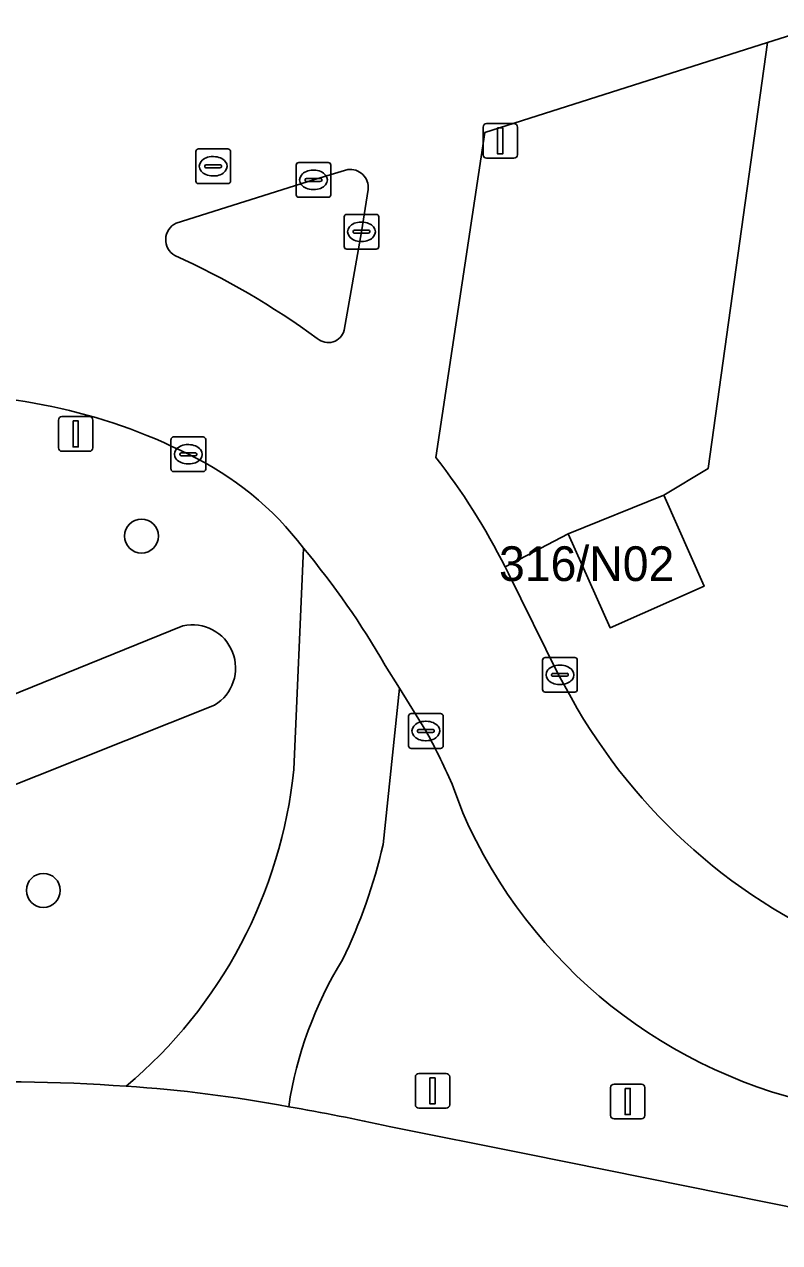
# Model space of a CAD drawing. Extents: x 161090 to 161692, y 379509 to 380907.
# Drawn here: x 161482.51 to 161504.29, y 379810.76 to 379845.87 of the extents above; entities that cross this region are included whole.
import ezdxf

# ---------------------------------------------------------------- set-up
doc = ezdxf.new("R2010")
doc.units = 0
for name, color, linetype in [('IMGEO_Boom', 7, 'Continuous'), ('IMGEO_Groenvoorziening', 7, 'Continuous'), ('IMGEO_Kolk', 7, 'Continuous'), ('IMGEO_Lichtmast', 7, 'Continuous'), ('IMGEO_Pand', 7, 'Continuous'), ('IMGEO_Pand_nummerreeks', 7, 'Continuous'), ('IMGEO_Rijbaan_lokaal_gesloten', 7, 'Continuous'), ('IMGEO_Rioolput', 7, 'Continuous'), ('IMGEO_Verkeerseiland_groen', 7, 'Continuous'), ('IMGEO_Verkeerseiland_open', 7, 'Continuous'), ('IMGEO_Voetpad_halfverhard', 7, 'Continuous'), ('IMGEO_Waterloop', 7, 'Continuous')]:
    doc.layers.add(name, color=color, linetype=linetype)

msp = doc.modelspace()

# ---------------------------------------------------------------- linework, layer by layer
at = {"layer": 'IMGEO_Boom'}
for centre in [(161485.888, 379831.123), (161483.057, 379820.91)]:
    msp.add_circle(centre, 0.489, dxfattribs=at)
at = {"layer": 'IMGEO_Groenvoorziening'}
for points in [[(161514.99, 379848.832), (161503.939, 379845.347), (161502.232, 379833.068), (161500.956, 379832.3), (161502.113, 379829.674), (161499.404, 379828.481), (161498.199, 379831.187), (161496.375, 379830.233), (161496.47, 379830.041), (161497.906, 379827.145), (161498.28, 379826.466)], [(161503.939, 379845.347), (161495.787, 379842.75), (161494.38, 379833.386)], [(161496.375, 379830.233), (161498.199, 379831.187), (161500.956, 379832.3), (161502.232, 379833.068), (161503.939, 379845.347)], [(161490.284, 379824.397), (161490.559, 379830.777)], [(161487.997, 379826.248), (161463.782, 379816.609), (161462.95, 379818.759), (161487.084, 379828.537)]]:
    msp.add_lwpolyline(points, dxfattribs=at)
for centre, radius, start, end in [((161480.014, 379819.128), 16.069, 63.2743, 93.106), ((161483.32, 379825.278), 9.091, 37.2239, 64.4573), ((161479.54, 379821.788), 18.834, 26.6382, 38.0073), ((161487.354, 379827.318), 1.248, 301.0173, 102.4732), ((161512.831, 379834.579), 16.66, 209.1437, 248.1335), ((161476.574, 379825.81), 13.782, 310.0851, 354.1164), ((161481.636, 379760.171), 55.226, 86.0407, 92.3337)]:
    msp.add_arc(centre, radius, start, end, dxfattribs=at)
at = {"layer": 'IMGEO_Kolk'}
for p, q in [((161490.349, 379840.962), (161490.349, 379841.814)), ((161490.424, 379841.888), (161491.276, 379841.888)), ((161490.837, 379841.668), (161490.862, 379841.668)), ((161491.35, 379841.814), (161491.35, 379840.962)), ((161490.608, 379841.382), (161490.608, 379841.394)), ((161491.046, 379841.345), (161490.648, 379841.345)), ((161490.651, 379841.431), (161491.049, 379841.431)), ((161491.092, 379841.394), (161491.092, 379841.382)), ((161490.86, 379841.108), (161490.835, 379841.108)), ((161491.276, 379840.888), (161490.424, 379840.888)), ((161491.732, 379839.468), (161491.732, 379840.32)), ((161491.807, 379840.394), (161492.659, 379840.394)), ((161492.733, 379840.32), (161492.733, 379839.468)), ((161491.991, 379839.888), (161491.991, 379839.9)), ((161492.034, 379839.937), (161492.432, 379839.937)), ((161492.22, 379840.174), (161492.245, 379840.174)), ((161492.475, 379839.9), (161492.475, 379839.888)), ((161492.429, 379839.851), (161492.031, 379839.851)), ((161492.243, 379839.614), (161492.218, 379839.614)), ((161492.659, 379839.394), (161491.807, 379839.394)), ((161486.739, 379833.054), (161486.739, 379833.906)), ((161486.814, 379833.98), (161487.666, 379833.98)), ((161487.74, 379833.906), (161487.74, 379833.054)), ((161487.227, 379833.76), (161487.252, 379833.76)), ((161486.998, 379833.474), (161486.998, 379833.486)), ((161487.436, 379833.437), (161487.038, 379833.437)), ((161487.041, 379833.523), (161487.439, 379833.523)), ((161487.25, 379833.2), (161487.225, 379833.2)), ((161487.482, 379833.486), (161487.482, 379833.474)), ((161487.666, 379832.98), (161486.814, 379832.98)), ((161497.531, 379827.623), (161498.383, 379827.623)), ((161497.456, 379826.697), (161497.456, 379827.549)), ((161497.944, 379827.403), (161497.969, 379827.403)), ((161498.457, 379827.549), (161498.457, 379826.697)), ((161497.715, 379827.117), (161497.715, 379827.129)), ((161498.153, 379827.08), (161497.755, 379827.08)), ((161497.758, 379827.166), (161498.156, 379827.166)), ((161498.199, 379827.129), (161498.199, 379827.117)), ((161498.383, 379826.623), (161497.531, 379826.623)), ((161497.967, 379826.843), (161497.942, 379826.843)), ((161493.59, 379825.078), (161493.59, 379825.93)), ((161493.665, 379826.004), (161494.517, 379826.004)), ((161494.591, 379825.93), (161494.591, 379825.078)), ((161493.849, 379825.498), (161493.849, 379825.51)), ((161493.892, 379825.547), (161494.29, 379825.547)), ((161494.078, 379825.784), (161494.103, 379825.784)), ((161494.333, 379825.51), (161494.333, 379825.498)), ((161494.287, 379825.461), (161493.889, 379825.461)), ((161494.101, 379825.224), (161494.076, 379825.224)), ((161494.517, 379825.004), (161493.665, 379825.004))]:
    msp.add_line(p, q, dxfattribs=at)
for points in [[(161490.349, 379840.962), (161490.349, 379841.814)], [(161490.424, 379841.888), (161491.276, 379841.888)], [(161491.35, 379841.814), (161491.35, 379840.962)], [(161491.276, 379840.888), (161490.424, 379840.888)], [(161491.732, 379839.468), (161491.732, 379840.32)], [(161491.807, 379840.394), (161492.659, 379840.394)], [(161492.733, 379840.32), (161492.733, 379839.468)], [(161492.659, 379839.394), (161491.807, 379839.394)], [(161486.739, 379833.054), (161486.739, 379833.906)], [(161486.814, 379833.98), (161487.666, 379833.98)], [(161487.74, 379833.906), (161487.74, 379833.054)], [(161487.666, 379832.98), (161486.814, 379832.98)], [(161497.531, 379827.623), (161498.383, 379827.623)], [(161497.456, 379826.697), (161497.456, 379827.549)], [(161498.457, 379827.549), (161498.457, 379826.697)], [(161498.383, 379826.623), (161497.531, 379826.623)], [(161493.59, 379825.078), (161493.59, 379825.93)], [(161493.665, 379826.004), (161494.517, 379826.004)], [(161494.591, 379825.93), (161494.591, 379825.078)], [(161494.517, 379825.004), (161493.665, 379825.004)]]:
    msp.add_lwpolyline(points, dxfattribs=at)
for centre, radius, start, end in [((161490.426, 379841.812), 0.0765, 91.552, 178.448), ((161490.426, 379841.812), 0.0765, 91.552, 178.448), ((161491.274, 379841.812), 0.0765, 1.552, 88.448), ((161491.274, 379841.812), 0.0765, 1.552, 88.448), ((161490.648, 379841.391), 0.0403, 85.8775, 175.7526), ((161490.645, 379841.381), 0.0366, 178.938, 274.7102), ((161491.049, 379841.388), 0.043, 264.8664, 352.4533), ((161491.053, 379841.393), 0.0386, 1.7309, 96.639), ((161490.426, 379840.964), 0.0765, 181.552, 268.448), ((161490.426, 379840.964), 0.0765, 181.552, 268.448), ((161491.274, 379840.964), 0.0765, 271.552, 358.448), ((161491.274, 379840.964), 0.0765, 271.552, 358.448), ((161491.809, 379840.318), 0.0765, 91.552, 178.448), ((161491.809, 379840.318), 0.0765, 91.552, 178.448), ((161492.657, 379840.318), 0.0765, 1.552, 88.448), ((161492.657, 379840.318), 0.0765, 1.552, 88.448), ((161492.031, 379839.897), 0.0403, 85.8775, 175.7526), ((161492.028, 379839.887), 0.0366, 178.938, 274.7102), ((161492.432, 379839.894), 0.043, 264.8664, 352.4533), ((161492.436, 379839.899), 0.0386, 1.7309, 96.639), ((161491.809, 379839.47), 0.0765, 181.552, 268.448), ((161491.809, 379839.47), 0.0765, 181.552, 268.448), ((161492.657, 379839.47), 0.0765, 271.552, 358.448), ((161492.657, 379839.47), 0.0765, 271.552, 358.448), ((161486.816, 379833.904), 0.0765, 91.552, 178.448), ((161486.816, 379833.904), 0.0765, 91.552, 178.448), ((161487.664, 379833.904), 0.0765, 1.552, 88.448), ((161487.664, 379833.904), 0.0765, 1.552, 88.448), ((161487.038, 379833.483), 0.0403, 85.8775, 175.7526), ((161487.035, 379833.473), 0.0366, 178.938, 274.7102), ((161487.439, 379833.48), 0.043, 264.8664, 352.4533), ((161487.443, 379833.485), 0.0386, 1.7309, 96.639), ((161486.816, 379833.056), 0.0765, 181.552, 268.448), ((161486.816, 379833.056), 0.0765, 181.552, 268.448), ((161487.664, 379833.056), 0.0765, 271.552, 358.448), ((161487.664, 379833.056), 0.0765, 271.552, 358.448), ((161497.533, 379827.547), 0.0765, 91.552, 178.448), ((161497.533, 379827.547), 0.0765, 91.552, 178.448), ((161498.381, 379827.547), 0.0765, 1.552, 88.448), ((161498.381, 379827.547), 0.0765, 1.552, 88.448), ((161497.755, 379827.126), 0.0403, 85.8775, 175.7526), ((161497.752, 379827.116), 0.0366, 178.938, 274.7102), ((161498.156, 379827.123), 0.043, 264.8664, 352.4533), ((161498.16, 379827.128), 0.0386, 1.7309, 96.639), ((161497.533, 379826.699), 0.0765, 181.552, 268.448), ((161497.533, 379826.699), 0.0765, 181.552, 268.448), ((161498.381, 379826.699), 0.0765, 271.552, 358.448), ((161498.381, 379826.699), 0.0765, 271.552, 358.448), ((161493.667, 379825.928), 0.0765, 91.552, 178.448), ((161493.667, 379825.928), 0.0765, 91.552, 178.448), ((161494.515, 379825.928), 0.0765, 1.552, 88.448), ((161494.515, 379825.928), 0.0765, 1.552, 88.448), ((161493.889, 379825.507), 0.0403, 85.8775, 175.7526), ((161493.886, 379825.497), 0.0366, 178.938, 274.7102), ((161494.29, 379825.504), 0.043, 264.8664, 352.4533), ((161494.294, 379825.509), 0.0386, 1.7309, 96.639), ((161493.667, 379825.08), 0.0765, 181.552, 268.448), ((161493.667, 379825.08), 0.0765, 181.552, 268.448), ((161494.515, 379825.08), 0.0765, 271.552, 358.448), ((161494.515, 379825.08), 0.0765, 271.552, 358.448)]:
    msp.add_arc(centre, radius, start, end, dxfattribs=at)
for centre, major_axis, ratio, start_param, end_param in [((161490.836, 379841.388), (-0.387, 0.002), 0.722429, 4.712389, 7.853982), ((161490.861, 379841.388), (-0.39, 0.002), 0.717154, 1.570796, 4.712389), ((161492.219, 379839.894), (-0.387, 0.002), 0.722429, 4.712389, 7.853982), ((161492.244, 379839.894), (-0.39, 0.002), 0.717154, 1.570796, 4.712389), ((161487.226, 379833.48), (-0.387, 0.002), 0.722429, 4.712389, 7.853982), ((161487.251, 379833.48), (-0.39, 0.002), 0.717154, 1.570796, 4.712389), ((161497.943, 379827.123), (-0.387, 0.002), 0.722429, 4.712389, 7.853982), ((161497.968, 379827.123), (-0.39, 0.002), 0.717154, 1.570796, 4.712389), ((161494.077, 379825.504), (-0.387, 0.002), 0.722429, 4.712389, 7.853982), ((161494.102, 379825.504), (-0.39, 0.002), 0.717154, 1.570796, 4.712389)]:
    msp.add_ellipse(centre, major_axis=major_axis, ratio=ratio, start_param=start_param, end_param=end_param, dxfattribs=at)
at = {"layer": 'IMGEO_Lichtmast'}
for p, q in [((161495.74, 379842.112), (161495.74, 379842.912)), ((161495.74, 379842.912), (161495.74, 379842.112)), ((161495.84, 379843.012), (161496.63, 379843.012)), ((161496.63, 379843.012), (161495.84, 379843.012)), ((161496.73, 379842.912), (161496.73, 379842.112)), ((161496.73, 379842.112), (161496.73, 379842.912)), ((161496.63, 379842.012), (161495.84, 379842.012)), ((161495.84, 379842.012), (161496.63, 379842.012)), ((161483.495, 379833.666), (161483.495, 379834.466)), ((161483.495, 379834.466), (161483.495, 379833.666)), ((161483.595, 379834.566), (161484.385, 379834.566)), ((161484.385, 379834.566), (161483.595, 379834.566)), ((161484.485, 379834.466), (161484.485, 379833.666)), ((161484.485, 379833.666), (161484.485, 379834.466)), ((161484.385, 379833.566), (161483.595, 379833.566)), ((161483.595, 379833.566), (161484.385, 379833.566)), ((161493.787, 379814.732), (161493.787, 379815.532)), ((161493.787, 379815.532), (161493.787, 379814.732)), ((161493.887, 379815.632), (161494.677, 379815.632)), ((161494.677, 379815.632), (161493.887, 379815.632)), ((161494.777, 379815.532), (161494.777, 379814.732)), ((161494.777, 379814.732), (161494.777, 379815.532)), ((161499.517, 379815.325), (161500.307, 379815.325)), ((161500.307, 379815.325), (161499.517, 379815.325)), ((161499.417, 379814.425), (161499.417, 379815.225)), ((161499.417, 379815.225), (161499.417, 379814.425)), ((161500.407, 379815.225), (161500.407, 379814.425)), ((161500.407, 379814.425), (161500.407, 379815.225)), ((161494.677, 379814.632), (161493.887, 379814.632)), ((161493.887, 379814.632), (161494.677, 379814.632)), ((161500.307, 379814.325), (161499.517, 379814.325)), ((161499.517, 379814.325), (161500.307, 379814.325))]:
    msp.add_line(p, q, dxfattribs=at)
for points in [[(161496.16, 379842.887), (161496.31, 379842.887), (161496.31, 379842.137), (161496.16, 379842.137), (161496.16, 379842.887)], [(161483.915, 379834.441), (161484.065, 379834.441), (161484.065, 379833.691), (161483.915, 379833.691), (161483.915, 379834.441)], [(161494.207, 379815.507), (161494.357, 379815.507), (161494.357, 379814.757), (161494.207, 379814.757), (161494.207, 379815.507)], [(161499.837, 379815.2), (161499.987, 379815.2), (161499.987, 379814.45), (161499.837, 379814.45), (161499.837, 379815.2)]]:
    msp.add_lwpolyline(points, dxfattribs=at)
for centre, start, end in [((161495.84, 379842.912), 90, 180), ((161495.84, 379842.912), 90, 180), ((161496.63, 379842.912), 0, 90), ((161496.63, 379842.912), 360, 90), ((161495.84, 379842.112), 180, 270), ((161495.84, 379842.112), 180, 270), ((161496.63, 379842.112), 270, 0), ((161496.63, 379842.112), 270, 0), ((161483.595, 379834.466), 90, 180), ((161483.595, 379834.466), 90, 180), ((161484.385, 379834.466), 0, 90), ((161484.385, 379834.466), 360, 90), ((161483.595, 379833.666), 180, 270), ((161483.595, 379833.666), 180, 270), ((161484.385, 379833.666), 270, 0), ((161484.385, 379833.666), 270, 0), ((161493.887, 379815.532), 90, 180), ((161493.887, 379815.532), 90, 180), ((161494.677, 379815.532), 0, 90), ((161494.677, 379815.532), 360, 90), ((161499.517, 379815.225), 90, 180), ((161499.517, 379815.225), 90, 180), ((161500.307, 379815.225), 0, 90), ((161500.307, 379815.225), 360, 90), ((161493.887, 379814.732), 180, 270), ((161493.887, 379814.732), 180, 270), ((161494.677, 379814.732), 270, 0), ((161494.677, 379814.732), 270, 0), ((161499.517, 379814.425), 180, 270), ((161499.517, 379814.425), 180, 270), ((161500.307, 379814.425), 270, 0), ((161500.307, 379814.425), 270, 0)]:
    msp.add_arc(centre, 0.1, start, end, dxfattribs=at)
at = {"layer": 'IMGEO_Pand'}
msp.add_lwpolyline([(161498.199, 379831.187), (161499.404, 379828.481), (161502.113, 379829.674), (161500.956, 379832.3)], close=True, dxfattribs=at)
at = {"layer": 'IMGEO_Rijbaan_lokaal_gesloten'}
for points in [[(161494.38, 379833.386), (161495.787, 379842.75), (161503.939, 379845.347), (161514.99, 379848.832), (161515.31, 379848.937), (161514.537, 379852.083), (161496.568, 379846.544)], [(161486.884, 379840.14), (161490.85, 379841.388), (161491.835, 379841.685)], [(161492.426, 379841.113), (161492.233, 379839.894)], [(161492.233, 379839.894), (161491.736, 379837.053)], [(161498.28, 379826.466), (161497.906, 379827.145), (161496.47, 379830.041), (161496.375, 379830.233)], [(161492.921, 379827.39), (161493.327, 379826.735), (161494.091, 379825.504)], [(161494.891, 379823.867), (161495.157, 379823.146)], [(161509.666, 379810.757), (161496.987, 379813.314), (161493.035, 379814.104)]]:
    msp.add_lwpolyline(points, dxfattribs=at)
for centre, radius, start, end in [((161491.907, 379841.168), 0.522, 353.9493, 97.9226), ((161487.114, 379839.666), 0.527, 115.8637, 239.8257), ((161477.292, 379818.055), 23.214, 53.9329, 65.6895), ((161491.275, 379837.178), 0.478, 228.6946, 344.8256), ((161480.014, 379819.128), 16.069, 63.2743, 93.106), ((161483.32, 379825.278), 9.091, 37.2239, 64.4573), ((161479.54, 379821.788), 18.834, 26.6382, 38.0073), ((161472.344, 379815.557), 23.736, 29.9009, 39.8808), ((161512.831, 379834.579), 16.66, 209.1437, 248.1335), ((161478.103, 379816.677), 18.263, 23.1854, 28.904), ((161508.497, 379828.972), 14.557, 203.5903, 259.3176), ((161481.636, 379760.171), 55.226, 86.0407, 92.3337), ((161482.82, 379775.556), 39.796, 79.409, 86.2116), ((161478.722, 379748.924), 66.733, 77.61461, 80.1532)]:
    msp.add_arc(centre, radius, start, end, dxfattribs=at)
at = {"layer": 'IMGEO_Rioolput'}
for p, q in [((161487.456, 379841.355), (161487.456, 379842.207)), ((161487.531, 379842.281), (161488.383, 379842.281)), ((161487.944, 379842.061), (161487.969, 379842.061)), ((161488.457, 379842.207), (161488.457, 379841.355)), ((161487.715, 379841.775), (161487.715, 379841.787)), ((161488.153, 379841.738), (161487.755, 379841.738)), ((161487.758, 379841.824), (161488.156, 379841.824)), ((161488.199, 379841.787), (161488.199, 379841.775)), ((161488.383, 379841.281), (161487.531, 379841.281)), ((161487.967, 379841.501), (161487.942, 379841.501))]:
    msp.add_line(p, q, dxfattribs=at)
for points in [[(161487.456, 379841.355), (161487.456, 379842.207)], [(161487.531, 379842.281), (161488.383, 379842.281)], [(161488.457, 379842.207), (161488.457, 379841.355)], [(161488.383, 379841.281), (161487.531, 379841.281)]]:
    msp.add_lwpolyline(points, dxfattribs=at)
for centre, radius, start, end in [((161487.533, 379842.205), 0.0765, 91.552, 178.448), ((161487.533, 379842.205), 0.0765, 91.552, 178.448), ((161488.381, 379842.205), 0.0765, 1.552, 88.448), ((161488.381, 379842.205), 0.0765, 1.552, 88.448), ((161487.755, 379841.784), 0.0403, 85.8775, 175.7526), ((161487.752, 379841.774), 0.0366, 178.938, 274.7102), ((161488.156, 379841.781), 0.043, 264.8664, 352.4533), ((161488.16, 379841.786), 0.0386, 1.7309, 96.639), ((161487.533, 379841.357), 0.0765, 181.552, 268.448), ((161487.533, 379841.357), 0.0765, 181.552, 268.448), ((161488.381, 379841.357), 0.0765, 271.552, 358.448), ((161488.381, 379841.357), 0.0765, 271.552, 358.448)]:
    msp.add_arc(centre, radius, start, end, dxfattribs=at)
for centre, major_axis, ratio, start_param, end_param in [((161487.943, 379841.781), (-0.387, 0.002), 0.722429, 4.712389, 7.853982), ((161487.968, 379841.781), (-0.39, 0.002), 0.717154, 1.570796, 4.712389)]:
    msp.add_ellipse(centre, major_axis=major_axis, ratio=ratio, start_param=start_param, end_param=end_param, dxfattribs=at)
at = {"layer": 'IMGEO_Verkeerseiland_groen'}
for points in [[(161493.327, 379826.735), (161492.855, 379822.23)], [(161494.091, 379825.504), (161493.327, 379826.735)], [(161495.157, 379823.146), (161494.891, 379823.867)], [(161493.035, 379814.104), (161496.987, 379813.314), (161509.666, 379810.757)]]:
    msp.add_lwpolyline(points, dxfattribs=at)
for centre, radius, start, end in [((161478.103, 379816.677), 18.263, 23.1854, 28.904), ((161508.497, 379828.972), 14.557, 203.5903, 259.3176), ((161477.388, 379825.804), 15.875, 334.257, 346.9893), ((161501.281, 379812.989), 11.274, 148.3214, 171.402), ((161478.722, 379748.924), 66.733, 77.61461, 80.1532)]:
    msp.add_arc(centre, radius, start, end, dxfattribs=at)
at = {"layer": 'IMGEO_Verkeerseiland_open'}
for points in [[(161491.835, 379841.685), (161490.85, 379841.388), (161486.884, 379840.14)], [(161492.233, 379839.894), (161492.426, 379841.113)], [(161491.736, 379837.053), (161492.233, 379839.894)]]:
    msp.add_lwpolyline(points, dxfattribs=at)
for centre, radius, start, end in [((161491.907, 379841.168), 0.522, 353.9493, 97.9226), ((161487.114, 379839.666), 0.527, 115.8637, 239.8257), ((161477.292, 379818.055), 23.214, 53.9329, 65.6895), ((161491.275, 379837.178), 0.478, 228.6946, 344.8256)]:
    msp.add_arc(centre, radius, start, end, dxfattribs=at)
at = {"layer": 'IMGEO_Voetpad_halfverhard'}
for points in [[(161490.559, 379830.777), (161490.284, 379824.397)], [(161493.327, 379826.735), (161492.921, 379827.39)], [(161492.855, 379822.23), (161493.327, 379826.735)]]:
    msp.add_lwpolyline(points, dxfattribs=at)
for centre, radius, start, end in [((161472.344, 379815.557), 23.736, 29.9009, 39.8808), ((161476.574, 379825.81), 13.782, 310.0851, 354.1164), ((161477.388, 379825.804), 15.875, 334.257, 346.9893), ((161501.281, 379812.989), 11.274, 148.3214, 171.402), ((161482.82, 379775.556), 39.796, 79.409, 86.2116)]:
    msp.add_arc(centre, radius, start, end, dxfattribs=at)
at = {"layer": 'IMGEO_Waterloop'}
msp.add_lwpolyline([(161487.084, 379828.537), (161462.95, 379818.759), (161463.782, 379816.609), (161487.997, 379826.248)], dxfattribs=at)
msp.add_arc((161487.354, 379827.318), 1.248, 301.0173, 102.4732, dxfattribs=at)

# ---------------------------------------------------------------- texts
at = {"layer": 'IMGEO_Pand_nummerreeks'}
msp.add_text('316/N02', height=1, dxfattribs=at).set_placement((161496.2, 379829.827))

doc.saveas('drawing.dxf')
